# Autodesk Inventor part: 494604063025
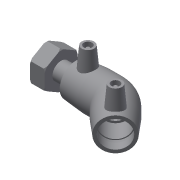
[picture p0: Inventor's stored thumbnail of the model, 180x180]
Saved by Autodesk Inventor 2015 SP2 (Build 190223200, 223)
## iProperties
Created: 2017-06
Part Number: 494604063025
Material: Generic
Description: PLASSON 45° ELBOW FEMALE FREE NUT TRANSITION 63-2.1/2"
Document SubType Name: Modeling
Designer: KIM
Mass: 55.0731 g
Surface Area: 148.067 cm^2
Volume: 55.0731 cm^3
Density: 1 g/cm^3
Appearance: Default
Author: KIM
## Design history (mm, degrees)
derived "494604.ipt"
feature "Solid1::494604.ipt"
tag "TaggingFeature1"
body "Solid1"
other parameters: "d2" = 82, "d4" = 38.25, "d5" = 73.8, "d8" = 168 deg, "d10" = 22.8, "d11" = 7.6, "d29" = 59, "d30" = 15, "d31" = 53.55, "d34" = 5 deg, "d41" = 4, "d42" = 14, "d43" = 0, "d49" = 63, "d50" = 53.55, "d51" = 22.8, "d52" = 57.57, "d54" = 135 deg, "d86" = 36.9, "d87" = 135 deg, "d88" = 153, "d90" = 57, "d91" = 0, "d92" = 57, "d93" = 0, "d101" = 3, "d102" = 0, "d108" = 48, "d110" = 44, "d112" = 108.339, "d113" = 72.226, "d139" = 50.5582, "d140" = 48, "d141" = 22, "d142" = 2.2, "d143" = 4.4, "d144" = 17.6, "d145" = 57.7808, "d146" = 3.6113, "d150" = 0, "d151" = 3.15, "d_" = 63, "L_" = 197, "L_1" = 57, "D_" = 48, "A_" = 59, "d_2" = 12, "L_2" = 44, "G_" = 72.226, "D_1" = 82
